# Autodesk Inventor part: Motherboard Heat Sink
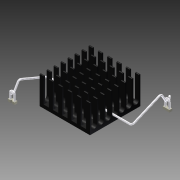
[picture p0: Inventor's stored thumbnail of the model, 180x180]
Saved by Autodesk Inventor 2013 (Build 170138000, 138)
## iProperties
Company: Autodesk Inc.
Created: 2005-12
Part Number: Motherboard Heat Sink
Document SubType Name: Modeling
Designer: Autodesk Inc.
Density: 1 g/cm^3
Mass: 11.4603 g
Surface Area: 154.607 cm^2
Volume: 11.4603 cm^3
Material: Allgemein
Title: PC Demo
Author: Autodesk Inc.
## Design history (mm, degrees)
sketch "Sketch1"
  geometry: L1 (0, 40.5)-(0, -33) reference; L2 (-34.5, 0)-(49.5, 0) reference; L3 (-22.5, 22.5)-(22.5, 22.5); L4 (22.5, 22.5)-(22.5, -22.5); L5 (22.5, -22.5)-(-22.5, -22.5); L6 (-22.5, -22.5)-(-22.5, 22.5)
  constraints: 8 end point, 2 parallel, 2 perpendicular, 1 horizontal, 2 other
  dimensions: "d0" = 45 distance of L3.start L3.end
extrude "Extrusion1" new body sketch "Sketch1" distance "d1" = 25; taper "d2" = 0 deg
sketch "Sketch2"
  geometry: L1 (22.5, 22.5)-(22.5, -22.5) reference; L2 (-22.5, 22.5)-(22.5, 22.5) reference; L3 (-22.5, -22.5)-(-22.5, 22.5) reference; L4 (-22.5, 21.25)-(22.5, 21.25); L5 (22.5, 21.25)-(22.5, 16.25); L6 (22.5, 16.25)-(-22.5, 16.25); L7 (-22.5, 16.25)-(-22.5, 21.25)
  constraints: 8 end point, 2 parallel, 2 point on line, 1 horizontal, 1 perpendicular
  dimensions: "d3" = 1.25 distance between parallel lines of L4 L2; "d4" = 5 distance between parallel lines of L6 L4
extrude "Extrusion2" cut sketch "Sketch2" distance "d5" = 22; taper "d6" = 0 deg
pattern_linear "Rectangular Pattern1" dims "d9" = 6.25
fillet "Fillet1" dims "d11" = 2.5
fillet "Fillet2" dims "d19" = 0.5
sketch "Sketch3"
  geometry: L1 (-22.5, 22.5)-(22.5, 22.5) reference; L2 (-22.5, 21.25)-(-22.5, 22.5) reference; L3 (22.5, -21.25)-(-22.5, -21.25) reference; L4 (-22.5, -22)-(-22.5, -21.75) reference; L5 (22.5, -21.75)-(22.5, -22) reference; L6 (-19, 22.5)-(-14.2, 22.5); L7 (-14.2, 22.5)-(-14.2, -22.5); L8 (-14.2, -22.5)-(-19, -22.5); L9 (-19, -22.5)-(-19, 22.5); L10 (22.5, -22)-(-22.5, -22) reference; L11 (-22.5, -21.75)-(22.5, -21.75) reference
  constraints: 8 end point, 2 parallel, 1 horizontal, 1 perpendicular, 1 point on line
  dimensions: "d12" = 3.5 distance between parallel lines of L2 L9; "d13" = 4.8 distance between parallel lines of L9 L7
extrude "Extrusion3" cut sketch "Sketch3" distance "d14" = 22; taper "d15" = 0 deg
pattern_linear "Rectangular Pattern2" dims "d18" = 8.3
workplane "Work Plane1"
sketch "3D Sketch1" dims "d26" = 2
  geometry: L1 through (25.144, 12.466) direction (-1, 0); 12 other entities
  constraints: 2 horizontal
  dimensions: "d27" = 2 dimension on L1 (= d26)
sketch "Sketch6"
  geometry: L1 (-13.459, 49.381)-(-8, 52.5) reference; A1 r 2 centre (-8.992, 54.236) between (-8, 52.5) and (-9.887, 56.025); 1 further point
  constraints: 2 point on circle, 1 centre point, 1 tangent
  dimensions: "d28" = 2 radius of A1
sweep "Sweep1" sketch "3D Sketch1", "Sketch6" dims "d30" = 0
workplane "Work Plane2"
sketch "Sketch7"
  geometry: L1 (0, 2)-(0, 8.886); L2 (-60, 8.992)-(-15, 8.992) reference; L3 (-15, 8.992)-(5.607, 8.992); L4 (-1.8, 2)-(-1.8, 8.992); L5 (1.8, 2)-(1.8, 8.992); C1 r 0.75 at (0, 2) reference; C2 r 0.75 at (0, 2) reference; A1 r 1.8 centre (0, 2) between (-1.8, 2) and (1.8, 2)
  constraints: 8 end point, 3 centre point, 2 perpendicular, 2 point on circle, 2 point on line, 2 tangent, 1 coincident, 1 collinear, 1 vertical, 4 other
  dimensions: "d31" = 1.8 radius of A1
sweep "Sweep2" sketch "Sketch7" dims "d33" = 0
sketch "Sketch9"
  geometry: L1 (37.5, 22.5)-(37.5, -22.5) reference; L2 (-35.1, 31.736)-(53.1, 31.736) reference; L3 (40.5, 32.986)-(40.5, 30.486); L4 (40.5, 30.486)-(34.5, 30.486); L5 (34.5, 30.486)-(34.5, 32.986); L6 (34.5, 32.986)-(36.762, 32.986); L7 (38.262, 32.986)-(40.5, 32.986); A1 r 0.5 centre (37.249, 33.411) between (37.512, 32.986) and (37.512, 32.986); A2 r 0.75 centre (37.512, 32.986) between (36.762, 32.986) and (38.262, 32.986)
  constraints: 10 end point, 4 point on circle, 3 parallel, 2 centre point, 2 horizontal, 2 perpendicular, 1 coincident, 3 other
  dimensions: "d34" = 6 distance of L5.end L3.start; "d35" = 2.5 distance of L3.start L3.end; "d38" = 1 diameter of A1; "d46" = 1.5 diameter of A2
extrude "Extrusion5" join sketch "Sketch9" distance "d39" = 2; taper "d40" = 0 deg
pattern_circular "Circular Pattern1" dims "d42" = 180 deg
sketch "Sketch10"
  geometry: C1 r 0.75 at (0, 0) reference
extrude "Extrusion6" join sketch "Sketch10" stored distance "d44" = 2; taper "d45" = 0 deg
body "Solid1"
sketch "Sketch4"
  geometry: L1 (0, 45)-(0, 0) reference; A1 r 2.5 centre (-5.5, 22.5) between (-5.5, 20) and (-5.5, 25) reference; 3 further points
  constraints: 1 horizontal alignment
  dimensions: "d21" = 1.5 distance of A1.centre point (-4, 22.5); "d22" = 15 distance from line of point (-15, 48.5) L1; "d23" = 26 vertical distance of A1.centre point (-15, 48.5); "d24" = 8 distance from line of L1 point (-8, 52.5); "d25" = 30 vertical distance of A1.centre point (-8, 52.5)
node "Projected Loop1"
sketch "Sketch5"
  geometry: C1 r 0.75 at (-4, 22.5); 1 further point
  constraints: 1 centre point, 1 coincident
  dimensions: "d29" = 1.5 diameter of C1
sketch "Sketch8"
  geometry: C1 r 0.75 at (39.3, 31.736); 1 further point
  constraints: 1 centre point, 1 coincident
  dimensions: "d32" = 1.5 diameter of C1
other parameters: "d20" = 15
